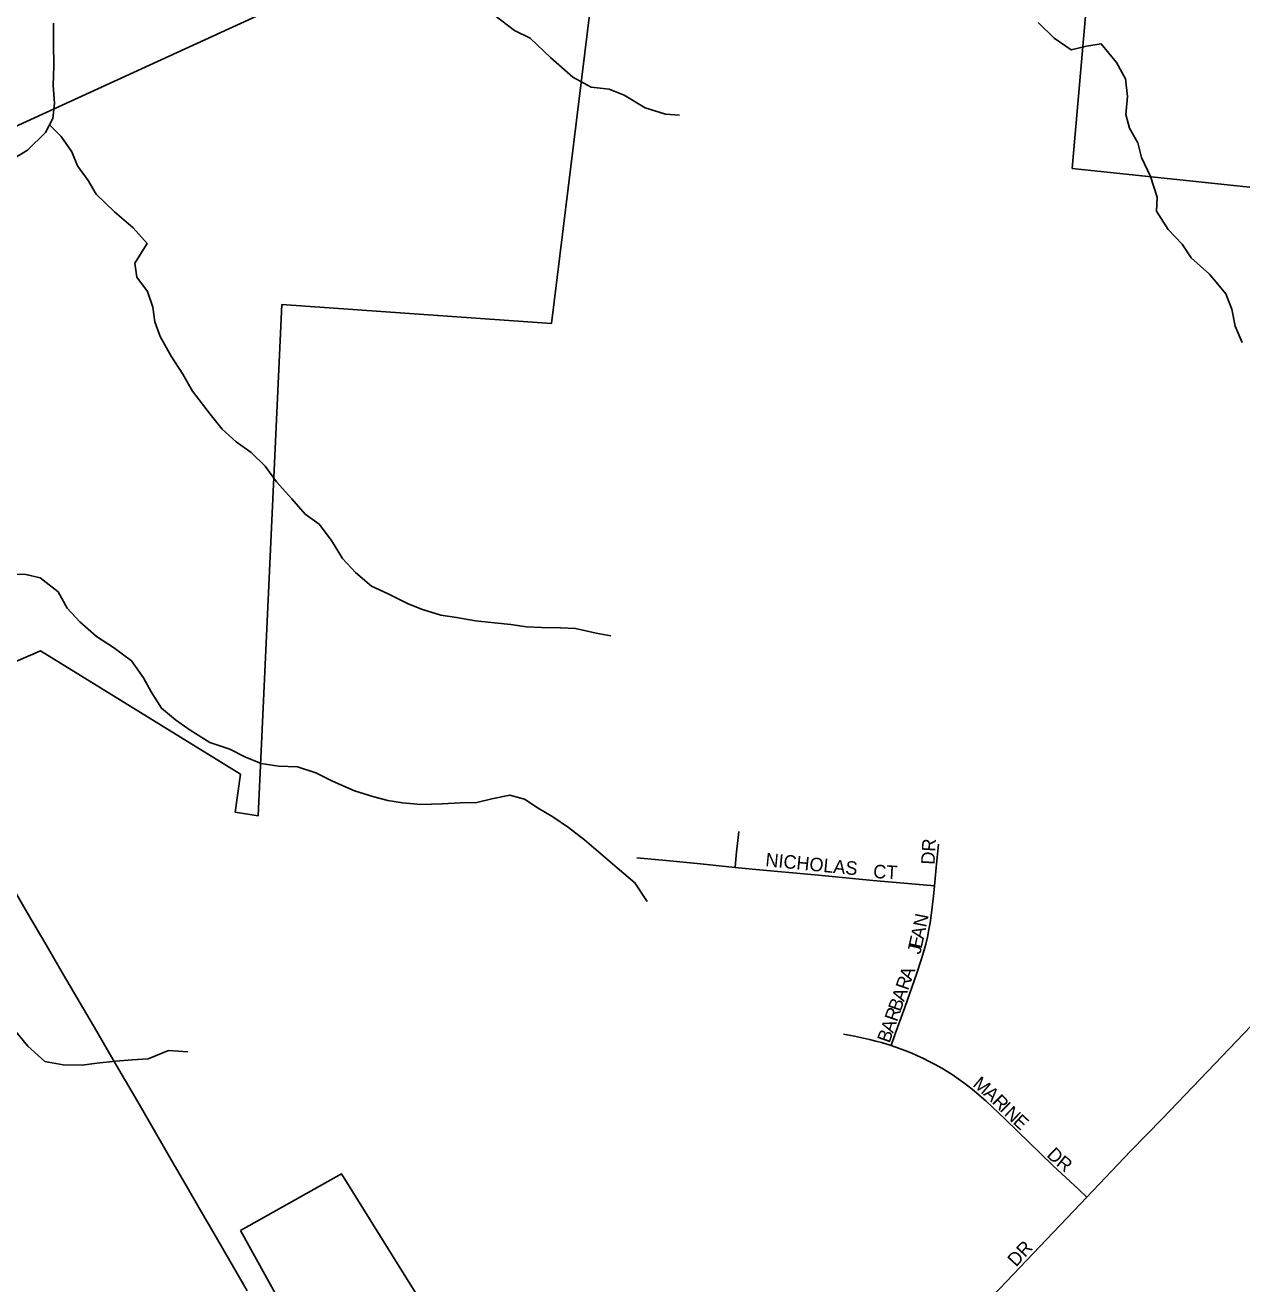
# Model space of a CAD drawing. Extents: x 1442749 to 1756758, y 235267 to 677782.
# Drawn here: x 1593799 to 1598304, y 520821 to 525480 of the extents above; entities that cross this region are included whole.
import ezdxf

# ---------------------------------------------------------------- set-up
doc = ezdxf.new("R2010")
doc.units = 0
for name, color, linetype in [('GM_X_City_Street', 7, 'Continuous'), ('GM_X_City_Street_Text', 7, 'Continuous'), ('GM_X_Corporation', 7, 'Continuous'), ('GM_X_Minor_River', 7, 'Continuous'), ('GM_X_State_Route', 7, 'Continuous')]:
    doc.layers.add(name, color=color, linetype=linetype)

msp = doc.modelspace()

# ---------------------------------------------------------------- linework, layer by layer
at = {"layer": 'GM_X_City_Street'}
for points in [[(1596427.3, 522362.5), (1596432, 522408), (1596441.2, 522495.8)], [(1597166.1, 522294), (1597172.4, 522361.8), (1597180.6, 522448.7)], [(1596064.1, 522398.3), (1596172.7, 522387.6), (1596298.8, 522375.1), (1596427.3, 522362.5)], [(1596427.3, 522362.5), (1596491.2, 522356.3), (1596735.8, 522333), (1596938, 522313.8), (1597123.5, 522297.7), (1597166.1, 522294)], [(1597005.6, 521702.8), (1597020.7, 521745.9), (1597055.4, 521844.2), (1597099.9, 521971.3), (1597116.7, 522020.2), (1597122.7, 522039.8), (1597127.9, 522057.5), (1597133.3, 522077.8), (1597139.7, 522104.4), (1597145.2, 522132.3), (1597149.6, 522157.3), (1597153.9, 522184.1), (1597162.6, 522255.8), (1597166.1, 522294)], [(1597729.7, 521142), (1597891.4, 521311.7), (1598009.9, 521432.8), (1598149.9, 521578.6), (1598445.4, 521888.5)], [(1596829.3, 521745), (1596870.2, 521737.2), (1596903.1, 521730.2), (1596925.6, 521725.2), (1596949.1, 521719.4), (1596970.1, 521713.8), (1597005.6, 521702.8)], [(1597005.6, 521702.8), (1597032.5, 521693.8), (1597060.2, 521683.4), (1597081.5, 521674.7), (1597102.4, 521665.5), (1597122.3, 521656.4), (1597143.7, 521645.5), (1597167.9, 521632.6), (1597192.5, 521618.7), (1597214.8, 521605.2), (1597234.4, 521592.9), (1597253.8, 521579.6), (1597274.7, 521564.7), (1597294.2, 521549.7), (1597313.4, 521534.4), (1597355.7, 521498), (1597427.2, 521430.5), (1597603.8, 521259.4), (1597701.3, 521168.5), (1597729.7, 521142)], [(1597356.9, 520751.2), (1597482, 520882), (1597729.7, 521142)]]:
    msp.add_lwpolyline(points, dxfattribs=at)
at = {"layer": 'GM_X_Corporation'}
msp.add_lwpolyline([(1598456.7, 526846.8), (1597823.9, 526643.2), (1597675.8, 524949.4), (1599329.7, 524775.5)], dxfattribs=at)
for points in [[(1593424.4, 522977), (1593855.8, 523163.9), (1594596.6, 522706.8), (1594576.3, 522566.9), (1594661.8, 522553.6), (1594748.7, 524445.5), (1595747.9, 524375.8), (1595911.5, 525709), (1595213.9, 525770.1), (1593215.5, 524854.2), (1592993.9, 524531.5), (1592743.5, 524131)], [(1594596, 521018), (1594860, 520540.6), (1595165.3, 519654.5), (1595548.8, 519784.8), (1595793.9, 520488.7), (1595323.9, 520659.6), (1594970.1, 521228.5)]]:
    msp.add_lwpolyline(points, close=True, dxfattribs=at)
at = {"layer": 'GM_X_Minor_River'}
for points in [[(1595152.3, 525978.5), (1595211.2, 525923.8), (1595250.6, 525867.2), (1595284.1, 525812.6), (1595323.5, 525754), (1595372.8, 525685.2), (1595426.2, 525624.4), (1595481.5, 525561.6), (1595533.1, 525518.9), (1595610.6, 525459.8), (1595668.4, 525431.1), (1595743.7, 525360), (1595827, 525286.8), (1595894.7, 525249.9), (1595960.8, 525243.2), (1596016.7, 525220.5), (1596094.3, 525173.4), (1596170.2, 525150.5), (1596222.2, 525145.9)], [(1593903.3, 525487.4), (1593904.4, 525411.2), (1593905.4, 525328.9), (1593902.6, 525256.7), (1593907.8, 525190.4), (1593901.2, 525134.3), (1593874.5, 525082.5), (1593807.6, 525017.1), (1593757.1, 524985.5)], [(1597549.1, 525489.8), (1597608.5, 525430.9), (1597672.1, 525388), (1597728.4, 525401.4), (1597782.6, 525410.8), (1597840, 525342), (1597873.3, 525281.4), (1597880.6, 525215.1), (1597873.8, 525149), (1597887.2, 525098.7), (1597918.6, 525044.2), (1597932, 524989.9), (1597965.3, 524919.3), (1597990.4, 524842.7), (1597987.8, 524790.6), (1598031.1, 524723.9), (1598082.6, 524669.2), (1598116, 524618.6), (1598183.5, 524557.7), (1598244.7, 524484.8), (1598266.1, 524428.3), (1598279.4, 524366), (1598304.8, 524305.5)], [(1593888.8, 525110.4), (1593932.4, 525067.8), (1593971.8, 525011.2), (1593993.3, 524958.8), (1594032.7, 524904.2), (1594062.2, 524853.7), (1594129.6, 524788.7), (1594199, 524729.7), (1594250.4, 524670.9), (1594205.5, 524599.2), (1594212.9, 524547), (1594252.4, 524494.4), (1594271.7, 524436), (1594279.1, 524381.8), (1594298.5, 524327.4), (1594339.7, 524254.7), (1594383, 524188), (1594418.4, 524125.4), (1594483.5, 524040.4), (1594528.9, 523983.7), (1594580.5, 523936.9), (1594636.2, 523898.2), (1594687.7, 523847.4), (1594729.1, 523788.8), (1594786.5, 523726), (1594835.9, 523669.2), (1594887.6, 523632.5), (1594933, 523571.8), (1594974.3, 523505.1), (1595021.8, 523454.4), (1595081.3, 523403.6), (1595143.1, 523374.8), (1595216.8, 523337.9), (1595270.7, 523317.2), (1595338.6, 523296.3), (1595396.6, 523287.7), (1595466.6, 523274.8), (1595536.7, 523268), (1595596.7, 523261.3), (1595654.7, 523252.6), (1595710.8, 523250), (1595781, 523249.2), (1595837, 523246.5), (1595913, 523229.6), (1595967, 523218.9)], [(1593727, 523449.2), (1593801.1, 523446.4), (1593855, 523433.7), (1593920.6, 523382.8), (1593953.9, 523322.2), (1594001.4, 523271.5), (1594062.9, 523216.7), (1594126.6, 523175.8), (1594192.1, 523126.9), (1594237.5, 523064.2), (1594264.9, 523011.8), (1594304.3, 522951.1), (1594355.9, 522908.4), (1594409.6, 522869.7), (1594483.2, 522824.7), (1594557.1, 522799.8), (1594612.8, 522771), (1594672.7, 522746.3), (1594736.7, 522737.5), (1594806.8, 522734.7), (1594874.7, 522711.9), (1594936.5, 522681.1), (1595018.2, 522646), (1595090.1, 522623.2), (1595142.1, 522610.5), (1595196.1, 522601.9), (1595264.1, 522595.1), (1595342.4, 522598.2), (1595410.5, 522601.4), (1595470.7, 522602.8), (1595527, 522616.1), (1595593.2, 522629.4), (1595647.2, 522614.8), (1595698.9, 522582.1), (1595752.6, 522549.4), (1595810.3, 522510.6), (1595869.9, 522463.8), (1595939.3, 522404.8), (1595990.9, 522360.1), (1596056.4, 522305.2), (1596101.7, 522236.5)], [(1593763.1, 521755.7), (1593808.5, 521701), (1593872, 521644.1), (1593940, 521631.3), (1594010.1, 521630.5), (1594064.3, 521637.9), (1594134.5, 521645.1), (1594194.7, 521650.5), (1594254.9, 521653.8), (1594329.4, 521685), (1594401.5, 521680.2)]]:
    msp.add_lwpolyline(points, dxfattribs=at)
at = {"layer": 'GM_X_State_Route'}
msp.add_lwpolyline([(1594621.2, 520795), (1594570.3, 520883), (1594497.2, 521008.1), (1594455.5, 521079.8), (1594389.8, 521193.4), (1594352.1, 521258.7), (1594286.6, 521372.4), (1594216.3, 521494.6), (1594125.2, 521650.4), (1594064.3, 521755.3), (1593941.3, 521964.6), (1593884.9, 522060.8), (1593799.3, 522208.3), (1593664.6, 522441.1)], dxfattribs=at)

# ---------------------------------------------------------------- texts
at = {"layer": 'GM_X_City_Street_Text'}
for s, rotation, p in [('DR', 86.8215, (1597165.8, 522371.3)), ('NICHOLAS', 354.2863, (1596538.1, 522366.9)), ('CT', 356.989, (1596938, 522323)), ('N', 78.7131, (1597135.3, 522138.4)), ('A', 77.4901, (1597125.5, 522094.3)), ('E', 77.5061, (1597117.9, 522059.9)), ('J', 77.4901, (1597113.2, 522038.4)), ('R', 70.6667, (1597067.5, 521904.6)), ('A', 70.1345, (1597080.6, 521941.9)), ('A', 70.674, (1597052.9, 521863.1)), ('B', 70.6667, (1597039.8, 521825.7)), ('R', 70.6664, (1597026.7, 521788.4)), ('B', 70.6664, (1596999.1, 521709.5)), ('A', 70.6813, (1597012.2, 521746.8)), ('M', 319.6674, (1597304.3, 521555)), ('A', 317.5204, (1597344.2, 521521.2)), ('R', 315.1374, (1597376.2, 521491.9)), ('I', 315.0618, (1597404.3, 521463.9)), ('N', 316.385, (1597420.8, 521447.5)), ('E', 317.2286, (1597453.2, 521416.6)), ('D', 316.3444, (1597577.9, 521294.7)), ('R', 321.2501, (1597613.2, 521261.3)), ('DR', 47.1199, (1597467.5, 520881.2))]:
    msp.add_text(s, height=50, rotation=rotation, dxfattribs=at).set_placement(p)

doc.saveas('drawing.dxf')
